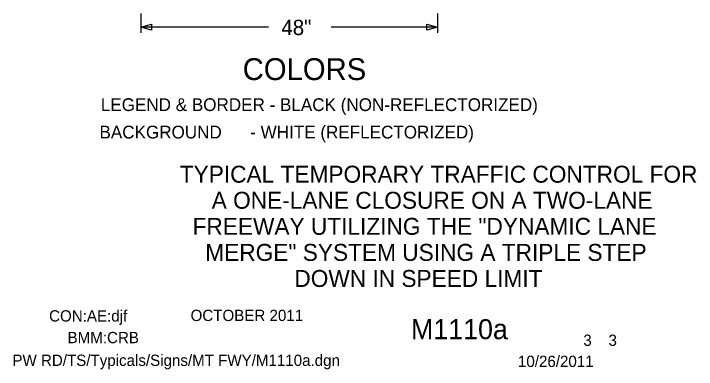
# Model space of a CAD drawing. Extents: x 15261 to 18126, y 1908 to 6555.
# Drawn here: x 17751.9 to 18126.4, y 2176.1 to 2371.3 of the extents above; entities that cross this region are included whole.
import ezdxf

# ---------------------------------------------------------------- set-up
doc = ezdxf.new("R2010")
doc.units = 0
doc.layers.add('BORDER_SIGNAL_WO', color=7, linetype='Continuous')
doc.layers.add('TYPICAL_TEXT_DIMEN_PR', color=7, linetype='Continuous')

msp = doc.modelspace()

# ---------------------------------------------------------------- linework, layer by layer
at = {"layer": 'TYPICAL_TEXT_DIMEN_PR'}
for p, q in [((17821.55, 2371.27), (17821.55, 2360.75)), ((17984.42, 2371.27), (17984.42, 2360.75)), ((17821.55, 2363.85), (17827.41, 2365.42)), ((17891.59, 2363.85), (17821.55, 2363.85)), ((17827.41, 2362.28), (17821.55, 2363.85)), ((17827.41, 2365.42), (17827.41, 2363.85)), ((17827.41, 2363.85), (17827.41, 2362.28)), ((17984.42, 2363.85), (17926.11, 2363.85)), ((17978.56, 2363.85), (17978.56, 2365.42)), ((17978.56, 2365.42), (17984.42, 2363.85)), ((17984.42, 2363.85), (17978.56, 2362.28)), ((17978.56, 2362.28), (17978.56, 2363.85))]:
    msp.add_line(p, q, dxfattribs=at)

# ---------------------------------------------------------------- texts
at = {"layer": 'BORDER_SIGNAL_WO'}
for s, height, p in [('TYPICAL TEMPORARY TRAFFIC CONTROL FOR', 9.3, (17842.98, 2278.54)), ('A ONE-LANE CLOSURE ON A TWO-LANE', 9.3, (17860.5, 2264.24)), ('FREEWAY UTILIZING THE "DYNAMIC LANE', 9.3, (17850, 2249.94)), ('MERGE" SYSTEM USING A TRIPLE STEP', 9.3, (17856.98, 2235.64)), ('DOWN IN SPEED LIMIT', 9.3, (17905.85, 2221.34)), ('CON:AE:djf  ', 6.2, (17771.3, 2202.35)), ('    OCTOBER 2011    ', 6.2, (17839.7, 2202.63)), ('    M1110a   ', 11, (17953.48, 2192.67)), ('BMM:CRB   ', 6.2, (17781.43, 2190.46)), (' 3    3 ', 6.2, (18062.06, 2188.99)), ('PW RD/TS/Typicals/Signs/MT FWY/M1110a.dgn      ', 6.2, (17751.17, 2178)), ('10/26/2011    ', 6.2, (18028.54, 2177.42))]:
    msp.add_text(s, height=height, dxfattribs=at).set_placement(p)
at = {"layer": 'TYPICAL_TEXT_DIMEN_PR'}
for s, height, p in [('48"', 8.4, (17898.72, 2359.51)), ('COLORS', 12, (17877.51, 2334.83)), ('LEGEND & BORDER - BLACK (NON-REFLECTORIZED)', 7, (17799.67, 2317.84)), ('BACKGROUND      - WHITE (REFLECTORIZED)', 7, (17798.94, 2302.79))]:
    msp.add_text(s, height=height, dxfattribs=at).set_placement(p)

doc.saveas('drawing.dxf')
